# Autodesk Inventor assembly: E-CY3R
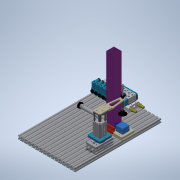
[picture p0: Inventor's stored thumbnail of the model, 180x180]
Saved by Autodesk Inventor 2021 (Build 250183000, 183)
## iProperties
Created: 2021-01
Part Number: E-CY3R
Material: Genérico
Document SubType Name: Assembly
Designer: ATOUZA
Author: ATOUZA
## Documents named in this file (20)
- D:\01 Paralaia\Grupos de Traballo\GT Maquetas\CAD 3D\E_AlimentaciónV1\EAV1.iam
- D:\01 Paralaia\Grupos de Traballo\GT Maquetas\CAD 3D\E_AlimentaciónV1\SMC_JP_MSQXB10AM9B0\MSQXB10A-M9B(0).iam
- D:\01 Paralaia\Grupos de Traballo\GT Maquetas\CAD 3D\E_AlimentaciónV1\SMC_JP_CDQMB2530M9B000\CDQMB25-30-M9B(0_0_0).iam
- D:\01 Paralaia\Grupos de Traballo\GT Maquetas\CAD 3D\E_AlimentaciónV1\Placa cilindro rotatorio.ipt
- D:\01 Paralaia\Grupos de Traballo\GT Maquetas\CAD 3D\E_AlimentaciónV1\Placa cilindro elevador.ipt
- D:\01 Paralaia\Grupos de Traballo\GT Maquetas\CAD 3D\E_AlimentaciónV1\SMC_JP_CD85N1650MBM9B000\CD85N16-50M-B-M9B(0__0_0).iam
- D:\01 Paralaia\Grupos de Traballo\GT Maquetas\CAD 3D\E_AlimentaciónV1\Cubo.ipt
- D:\01 Paralaia\Grupos de Traballo\GT Maquetas\CAD 3D\E_AlimentaciónV1\ZPT32SCK30\ZPT32CSK30-04-A10_(S) Silicon rubber.iam
- D:\01 Paralaia\Grupos de Traballo\GT Maquetas\CAD 3D\E_AlimentaciónV1\Alimentador.ipt
- D:\01 Paralaia\Grupos de Traballo\GT Maquetas\CAD 3D\E_AlimentaciónV1\LateralAlimentadorDcha.ipt
- D:\01 Paralaia\Grupos de Traballo\GT Maquetas\CAD 3D\E_AlimentaciónV1\EmpujadorCabeza.ipt
- D:\01 Paralaia\Grupos de Traballo\GT Maquetas\CAD 3D\E_AlimentaciónV1\EmpujadorHorizontal.ipt
- D:\01 Paralaia\Grupos de Traballo\GT Maquetas\CAD 3D\E_AlimentaciónV1\SoporteCilindro.ipt
- D:\01 Paralaia\Grupos de Traballo\GT Maquetas\CAD 3D\E_AlimentaciónV1\BrazoElevador.ipt
- D:\01 Paralaia\Grupos de Traballo\GT Maquetas\CAD 3D\E_AlimentaciónV1\BrazoVentosa.ipt
- D:\01 Paralaia\Grupos de Traballo\GT Maquetas\CAD 3D\E_AlimentaciónV1\Perfil 20x20 B R6.ipt
- D:\01 Paralaia\Grupos de Traballo\GT Maquetas\CAD 3D\E_AlimentaciónV1\LateralAlimentadorIzq.ipt
- D:\01 Paralaia\Grupos de Traballo\GT Maquetas\CAD 3D\E_AlimentaciónV1\PlacaDeslizaPieza.ipt
- D:\01 Paralaia\Grupos de Traballo\GT Maquetas\CAD 3D\E_AlimentaciónV1\TopePieza.ipt
- D:\01 Paralaia\Grupos de Traballo\GT Maquetas\CAD 3D\E_AlimentaciónV1\Electroválvulas\BloqueElectroválvulas.iam
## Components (34 placed, 19 different names)
1. MSQXB10A-M9B(0):1 [sub-assembly] — Coincidencia:7, Coincidencia:8, Coincidencia:9, Nivelación:10, Coincidencia:27, Nivelación:14, Ángulo:5
2. CDQMB25-30-M9B(0_0_0):1 [sub-assembly] — Nivelación:3, Insertar:1, Insertar:2, Insertar:9, Insertar:10
3. Placa cilindro rotatorio:1 — Coincidencia:4, Coincidencia:5, Coincidencia:6, Coincidencia:7, Coincidencia:8, Coincidencia:9, Ángulo:5
4. Placa cilindro elevador:1 — Nivelación:3, Coincidencia:4, Coincidencia:5, Coincidencia:6, Insertar:1, Insertar:2
5. CD85N16-50M-B-M9B(0__0_0):1 [sub-assembly] — Insertar:5, Coincidencia:21, Insertar:6
6. Cubo:1 — Ángulo:3, Coincidencia:23, Coincidencia:24, Coincidencia:25, Ángulo:4, Nivelación:10, Coincidencia:27, Nivelación:12, Coincidencia:32
7. ZPT32CSK30-04-A10_(S) Silicon rubber:1 [sub-assembly] — Ángulo:4, Coincidencia:28, Nivelación:11
8. Alimentador:1 — Coincidencia:12, Coincidencia:17, Coincidencia:22, Coincidencia:23, Coincidencia:31, Nivelación:15
9. LateralAlimentadorDcha — Coincidencia:17, Coincidencia:29, Nivelación:12, Coincidencia:32, Insertar:12
10. LateralAlimentadorIzq:1 — Coincidencia:31, Nivelación:15, Insertar:11
11. EmpujadorCabeza:1 — Insertar:3, Insertar:4, Ángulo:2, Ángulo:3, Coincidencia:21, Insertar:6, Coincidencia:22, Coincidencia:24, Coincidencia:35
12. EmpujadorHorizontal:1 — Insertar:3, Insertar:4
13. SoporteCilindro:1 — Insertar:5, Ángulo:2, Coincidencia:25
14. BrazoElevador:1 — Insertar:7, Insertar:8, Insertar:9, Insertar:10
15. BrazoVentosa:1 — Insertar:7, Insertar:8, Coincidencia:28, Nivelación:11
16. PlacaDeslizaPieza:1 — Nivelación:16, Nivelación:17, Coincidencia:33, Insertar:11, Insertar:12, Nivelación:18, Nivelación:19, Insertar:15, Insertar:16, Coincidencia:35
17. TopePieza:1 — Nivelación:18, Nivelación:19, Insertar:13, Insertar:14, Insertar:15, Insertar:16
18. TopePieza:2 — Insertar:13, Insertar:14
19. BloqueElectroválvulas:1 [sub-assembly] — Coincidencia:34, Nivelación:20
20. Perfil 20x20 B R6 480:1 — Nivelación:13
21. Perfil 20x20 B R6 480:2 — Coincidencia:34
22. Perfil 20x20 B R6 480:3
23. Perfil 20x20 B R6 480:4 — Nivelación:20
24. Perfil 20x20 B R6 480:5
25. Perfil 20x20 B R6 480:6
26. Perfil 20x20 B R6 480:7
27. Perfil 20x20 B R6 480:8
28. Perfil 20x20 B R6 480:9
29. Perfil 20x20 B R6 480:10
30. Perfil 20x20 B R6 480:11
31. Perfil 20x20 B R6 480:12
32. Perfil 20x20 B R6 480:13
33. Perfil 20x20 B R6 480:14
34. Perfil 20x20 B R6 480:15 — Nivelación:14
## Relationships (53: Mate 21, Insert 16, Flush 12, Angle 4)
- Nivelación:3 [Flush]: CDQMB25-30-M9B(0_0_0):1 ↔ Placa cilindro elevador:1
- Coincidencia:4 [Mate]: Placa cilindro rotatorio:1 ↔ Placa cilindro elevador:1
- Coincidencia:5 [Mate]: Placa cilindro rotatorio:1 ↔ Placa cilindro elevador:1
- Coincidencia:6 [Mate]: Placa cilindro rotatorio:1 ↔ Placa cilindro elevador:1
- Coincidencia:7 [Mate]: MSQXB10A-M9B(0):1 ↔ Placa cilindro rotatorio:1
- Coincidencia:8 [Mate]: MSQXB10A-M9B(0):1 ↔ Placa cilindro rotatorio:1
- Coincidencia:9 [Mate]: MSQXB10A-M9B(0):1 ↔ Placa cilindro rotatorio:1
- Insertar:1: CDQMB25-30-M9B(0_0_0):1 ↔ Placa cilindro elevador:1
- Insertar:2: CDQMB25-30-M9B(0_0_0):1 ↔ Placa cilindro elevador:1
- Coincidencia:12 [Mate]: Alimentador:1
- Coincidencia:17 [Mate]: Alimentador:1 ↔ LateralAlimentadorDcha
- Insertar:3: EmpujadorCabeza:1 ↔ EmpujadorHorizontal:1
- Insertar:4: EmpujadorCabeza:1 ↔ EmpujadorHorizontal:1
- Insertar:5: CD85N16-50M-B-M9B(0__0_0):1 ↔ SoporteCilindro:1
- Ángulo:2 [Angle]: EmpujadorCabeza:1 ↔ SoporteCilindro:1
- Ángulo:3 [Angle]: Cubo:1 ↔ EmpujadorCabeza:1
- Coincidencia:21 [Mate]: CD85N16-50M-B-M9B(0__0_0):1 ↔ EmpujadorCabeza:1
- Insertar:6: CD85N16-50M-B-M9B(0__0_0):1 ↔ EmpujadorCabeza:1
- Coincidencia:22 [Mate]: Alimentador:1 ↔ EmpujadorCabeza:1
- Coincidencia:23 [Mate]: Cubo:1 ↔ Alimentador:1
- Coincidencia:24 [Mate]: Cubo:1 ↔ EmpujadorCabeza:1
- Coincidencia:25 [Mate]: Cubo:1 ↔ SoporteCilindro:1
- Ángulo:4 [Angle]: Cubo:1 ↔ ZPT32CSK30-04-A10_(S) Silicon rubber:1
- Nivelación:10 [Flush]: MSQXB10A-M9B(0):1 ↔ Cubo:1
- Coincidencia:27 [Mate]: MSQXB10A-M9B(0):1 ↔ Cubo:1
- Insertar:7: BrazoElevador:1 ↔ BrazoVentosa:1
- Insertar:8: BrazoElevador:1 ↔ BrazoVentosa:1
- Insertar:9: CDQMB25-30-M9B(0_0_0):1 ↔ BrazoElevador:1
- Coincidencia:28 [Mate]: ZPT32CSK30-04-A10_(S) Silicon rubber:1 ↔ BrazoVentosa:1
- Insertar:10: CDQMB25-30-M9B(0_0_0):1 ↔ BrazoElevador:1
- Nivelación:11 [Flush]: ZPT32CSK30-04-A10_(S) Silicon rubber:1 ↔ BrazoVentosa:1
- Coincidencia:29 [Mate]: LateralAlimentadorDcha
- Nivelación:12 [Flush]: Cubo:1 ↔ LateralAlimentadorDcha
- Nivelación:13 [Flush]: Perfil 20x20 B R6 480:1
- Nivelación:14 [Flush]: MSQXB10A-M9B(0):1 ↔ Perfil 20x20 B R6 480:15
- Ángulo:5 [Angle]: MSQXB10A-M9B(0):1 ↔ Placa cilindro rotatorio:1
- Coincidencia:31 [Mate]: Alimentador:1 ↔ LateralAlimentadorIzq:1
- Nivelación:15 [Flush]: Alimentador:1 ↔ LateralAlimentadorIzq:1
- Coincidencia:32 [Mate]: Cubo:1 ↔ LateralAlimentadorDcha
- Nivelación:16 [Flush]: PlacaDeslizaPieza:1
- Nivelación:17 [Flush]: PlacaDeslizaPieza:1
- Coincidencia:33 [Mate]: PlacaDeslizaPieza:1
- Insertar:11: LateralAlimentadorIzq:1 ↔ PlacaDeslizaPieza:1
- Insertar:12: LateralAlimentadorDcha ↔ PlacaDeslizaPieza:1
- Nivelación:18 [Flush]: PlacaDeslizaPieza:1 ↔ TopePieza:1
- Nivelación:19 [Flush]: PlacaDeslizaPieza:1 ↔ TopePieza:1
- Insertar:13: TopePieza:1 ↔ TopePieza:2
- Insertar:14: TopePieza:1 ↔ TopePieza:2
- Insertar:15: PlacaDeslizaPieza:1 ↔ TopePieza:1
- Insertar:16: PlacaDeslizaPieza:1 ↔ TopePieza:1
- Coincidencia:34 [Mate]: BloqueElectroválvulas:1 ↔ Perfil 20x20 B R6 480:2
- Nivelación:20 [Flush]: BloqueElectroválvulas:1 ↔ Perfil 20x20 B R6 480:4
- Coincidencia:35 [Mate]: EmpujadorCabeza:1 ↔ PlacaDeslizaPieza:1
